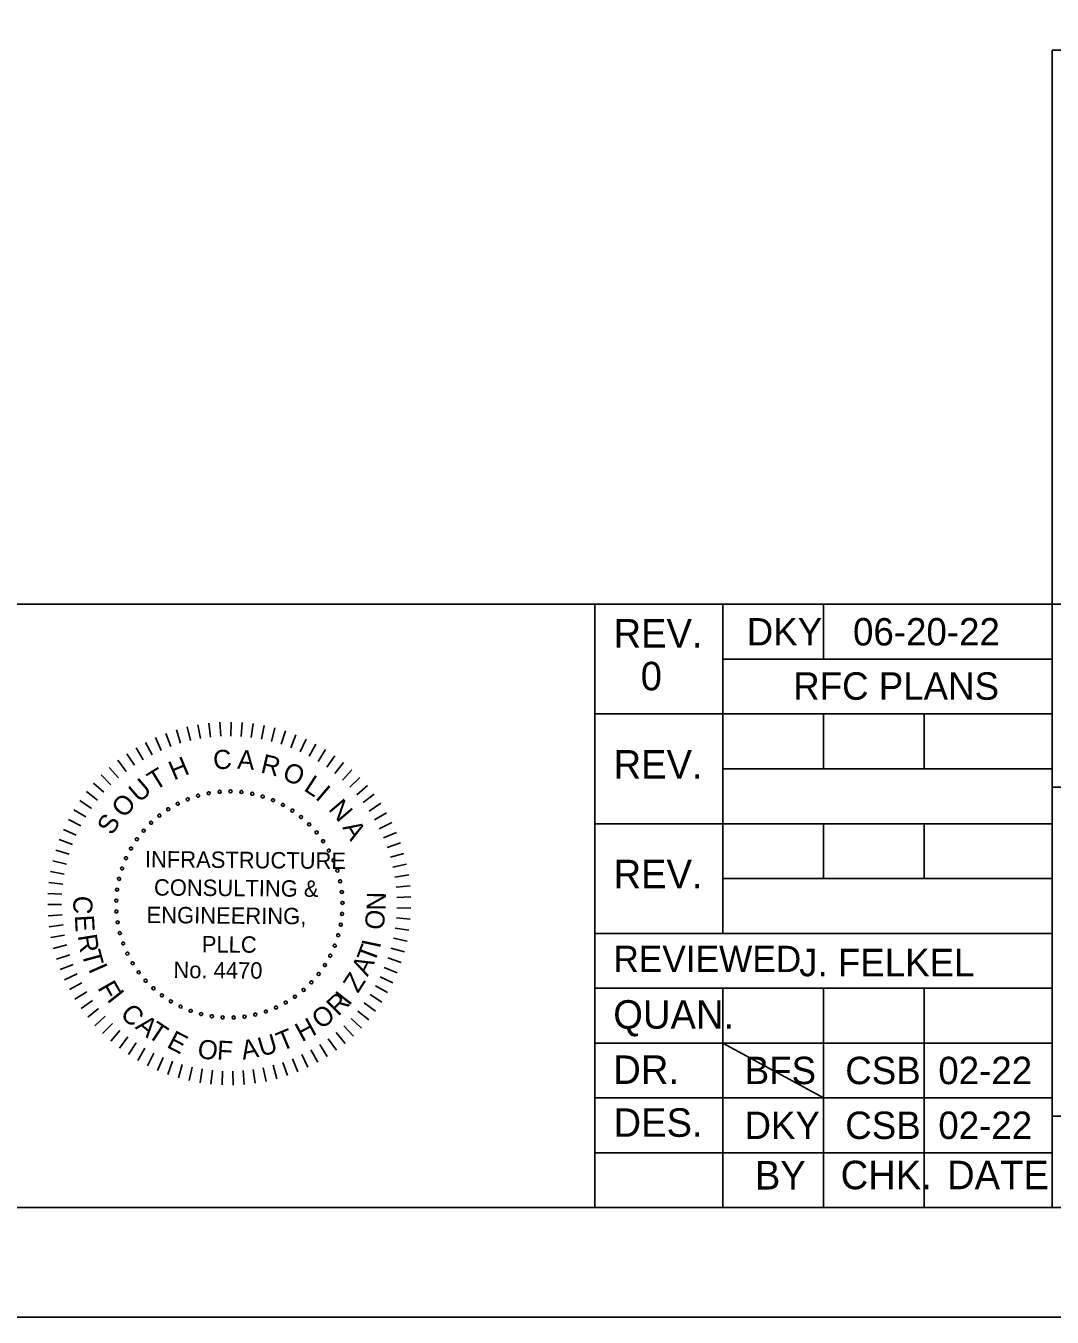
# Model space of a CAD drawing. Extents: x -133.1 to -97, y -1.7 to 20.3.
# Drawn here: x -107.74 to -103.06, y -1.69 to 4.2 of the extents above; entities that cross this region are included whole.
import ezdxf

# ---------------------------------------------------------------- set-up
doc = ezdxf.new("R2010")
doc.units = 0
for name, color, linetype in [('BR_BORDER LINES', 7, 'Continuous'), ('BR_TEXT', 7, 'Continuous'), ('Level 31', 7, 'Continuous')]:
    doc.layers.add(name, color=color, linetype=linetype)

msp = doc.modelspace()

# ---------------------------------------------------------------- linework, layer by layer
at = {"layer": 'BR_BORDER LINES'}
for p, q in [((-103.0585, -1.191), (-103.0585, 4.0855)), ((-103.0585, 4.0855), (-97.6416, 4.0855)), ((-110.5071, 1.5591), (-105.1419, 1.5591)), ((-105.1419, -1.191), (-105.1419, 1.5591)), ((-105.1419, 1.5591), (-97.6416, 1.5591)), ((-104.5585, 1.5591), (-104.5585, 0.059)), ((-104.1002, 1.3091), (-104.1002, 1.5591)), ((-104.5585, 1.3091), (-103.0585, 1.3091)), ((-105.1419, 1.0591), (-103.0585, 1.0591)), ((-104.1002, 0.809), (-104.1002, 1.0591)), ((-103.6418, 0.809), (-103.6418, 1.0591)), ((-104.5585, 0.809), (-103.0585, 0.809)), ((-103.0585, 0.7257), (-103.0585, 0.7257)), ((-103.0585, 0.7257), (-97.6414, 0.7257)), ((-105.1419, 0.559), (-103.0585, 0.559)), ((-104.1002, 0.309), (-104.1002, 0.559)), ((-103.6418, 0.309), (-103.6418, 0.559)), ((-104.5585, 0.309), (-103.0585, 0.309)), ((-105.1419, 0.059), (-103.0585, 0.059)), ((-105.1419, -0.191), (-103.0585, -0.191)), ((-104.5585, -0.191), (-104.5585, -1.191)), ((-104.1002, -0.191), (-104.1002, -1.191)), ((-103.6418, -0.191), (-103.6418, -1.191)), ((-105.1419, -0.441), (-103.0585, -0.441)), ((-105.1419, -0.691), (-103.0585, -0.691)), ((-103.0585, -0.7744), (-97.6416, -0.7744)), ((-105.1419, -0.941), (-103.0585, -0.941)), ((-131.3076, -1.191), (-97.6416, -1.191))]:
    msp.add_line(p, q, dxfattribs=at)
at = {"layer": 'BR_TEXT'}
for p, q in [((-106.9512, 1.01), (-106.9401, 0.9473)), ((-106.9012, 1.0172), (-106.894, 0.9539)), ((-106.8509, 1.0213), (-106.8476, 0.9578)), ((-106.8005, 1.0224), (-106.801, 0.9587)), ((-106.75, 1.0204), (-106.7544, 0.9569)), ((-106.6998, 1.0153), (-106.7081, 0.9522)), ((-106.65, 1.0071), (-106.6621, 0.9446)), ((-107.1439, 0.9513), (-107.1181, 0.8932)), ((-107.0972, 0.9704), (-107.0749, 0.9107)), ((-107.0494, 0.9866), (-107.0308, 0.9257)), ((-107.0007, 0.9998), (-106.9858, 0.9379)), ((-106.6007, 0.996), (-106.6166, 0.9343)), ((-106.5523, 0.9818), (-106.5719, 0.9213)), ((-106.5048, 0.9648), (-106.528, 0.9055)), ((-106.4584, 0.9448), (-106.4852, 0.8871)), ((-107.2335, 0.9049), (-107.2008, 0.8503)), ((-107.1895, 0.9295), (-107.1601, 0.873)), ((-106.4133, 0.9221), (-106.4436, 0.8661)), ((-106.3697, 0.8967), (-106.4034, 0.8426)), ((-107.3168, 0.8478), (-107.2776, 0.7976)), ((-107.276, 0.8776), (-107.24, 0.8251)), ((-106.3277, 0.8686), (-106.3646, 0.8167)), ((-106.2875, 0.8381), (-106.3275, 0.7885)), ((-107.3925, 0.7811), (-107.3475, 0.736)), ((-107.3557, 0.8156), (-107.3135, 0.7679)), ((-106.2493, 0.8051), (-106.2922, 0.7581)), ((-106.2131, 0.7699), (-106.2588, 0.7256)), ((-107.4272, 0.7444), (-107.3795, 0.7022)), ((-106.1791, 0.7326), (-106.2275, 0.6911)), ((-107.4895, 0.665), (-107.437, 0.6289)), ((-107.4595, 0.7056), (-107.4094, 0.6664)), ((-106.1475, 0.6932), (-106.1983, 0.6548)), ((-106.1184, 0.652), (-106.1714, 0.6167)), ((-107.5169, 0.6226), (-107.4623, 0.5897)), ((-106.0918, 0.6091), (-106.1469, 0.5771)), ((-107.5637, 0.5332), (-107.5055, 0.5072)), ((-107.5416, 0.5786), (-107.4852, 0.5491)), ((-106.0679, 0.5646), (-106.1248, 0.5361)), ((-107.5829, 0.4865), (-107.5233, 0.4641)), ((-106.0467, 0.5188), (-106.1052, 0.4938)), ((-106.0283, 0.4718), (-106.0883, 0.4504)), ((-107.5992, 0.4387), (-107.5384, 0.42)), ((-106.0129, 0.4237), (-106.0741, 0.406)), ((-107.6126, 0.3901), (-107.5507, 0.3751)), ((-106.0004, 0.3748), (-106.0625, 0.3608)), ((-107.623, 0.3407), (-107.5604, 0.3295)), ((-105.9909, 0.3252), (-106.0538, 0.3151)), ((-107.6348, 0.2404), (-107.5712, 0.237)), ((-107.6304, 0.2907), (-107.5672, 0.2834)), ((-105.9845, 0.2751), (-106.0479, 0.2689)), ((-107.636, 0.19), (-107.5723, 0.1904)), ((-105.9811, 0.2247), (-106.0448, 0.2224)), ((-107.6342, 0.1395), (-107.5706, 0.1438)), ((-105.9836, 0.1239), (-106.0471, 0.1292)), ((-105.9809, 0.1743), (-106.0445, 0.1758)), ((-107.6293, 0.0893), (-107.5661, 0.0974)), ((-105.9895, 0.0737), (-106.0525, 0.0829)), ((-107.6213, 0.0394), (-107.5588, 0.0514)), ((-107.6103, -0.0099), (-107.5487, 0.0059)), ((-105.9984, 0.024), (-106.0607, 0.0371)), ((-107.5964, -0.0584), (-107.5358, -0.0388)), ((-106.0252, -0.0733), (-106.0855, -0.0527)), ((-106.0103, -0.025), (-106.0717, -0.0082)), ((-107.5795, -0.106), (-107.5202, -0.0828)), ((-106.043, -0.1205), (-106.1019, -0.0963)), ((-107.5597, -0.1524), (-107.5019, -0.1256)), ((-107.5371, -0.1976), (-107.4811, -0.1673)), ((-106.0636, -0.1666), (-106.1209, -0.1389)), ((-107.5119, -0.2413), (-107.4578, -0.2077)), ((-106.1131, -0.2545), (-106.1667, -0.22)), ((-106.087, -0.2113), (-106.1426, -0.1802)), ((-107.484, -0.2834), (-107.4321, -0.2465)), ((-107.4536, -0.3237), (-107.404, -0.2837)), ((-106.1418, -0.2961), (-106.1931, -0.2584)), ((-107.4208, -0.362), (-107.3737, -0.3191)), ((-107.3857, -0.3983), (-107.3413, -0.3527)), ((-106.2065, -0.3735), (-106.2529, -0.3299)), ((-106.173, -0.3358), (-106.2219, -0.2951)), ((-107.3485, -0.4324), (-107.307, -0.3841)), ((-106.2801, -0.4426), (-106.3208, -0.3936)), ((-106.2423, -0.4092), (-106.2859, -0.3628)), ((-107.3092, -0.4642), (-107.2708, -0.4135)), ((-107.2681, -0.4935), (-107.2328, -0.4405)), ((-107.2253, -0.5203), (-107.1933, -0.4652)), ((-106.3616, -0.5021), (-106.3961, -0.4485)), ((-106.32, -0.4736), (-106.3576, -0.4222)), ((-107.1809, -0.5444), (-107.1523, -0.4875)), ((-107.1352, -0.5657), (-107.1101, -0.5072)), ((-107.0882, -0.5842), (-107.0668, -0.5243)), ((-106.5432, -0.5894), (-106.5637, -0.5291)), ((-106.4959, -0.5718), (-106.52, -0.5128)), ((-106.4498, -0.5513), (-106.4774, -0.4939)), ((-106.4049, -0.528), (-106.436, -0.4725)), ((-107.0402, -0.5998), (-107.0225, -0.5387)), ((-106.9913, -0.6125), (-106.9773, -0.5504)), ((-106.9418, -0.6221), (-106.9316, -0.5593)), ((-106.8918, -0.6288), (-106.8854, -0.5654)), ((-106.8414, -0.6323), (-106.8389, -0.5687)), ((-106.7909, -0.6328), (-106.7923, -0.5691)), ((-106.7405, -0.6302), (-106.7458, -0.5667)), ((-106.6903, -0.6245), (-106.6995, -0.5615)), ((-106.6406, -0.6158), (-106.6536, -0.5535)), ((-106.5915, -0.6041), (-106.6083, -0.5427))]:
    msp.add_line(p, q, dxfattribs=at)
for centre, start, end in [((-106.8527, 0.7043), 5.06529, 185.06529), ((-106.8029, 0.7062), 359.52683, 179.52683), ((-106.7531, 0.7033), 353.98837, 173.98837), ((-107.0431, 0.6496), 27.21914, 207.21914), ((-107.0431, 0.6496), 207.21914, 27.21914), ((-106.9977, 0.6702), 21.68068, 201.68068), ((-106.9977, 0.6702), 201.68068, 21.68068), ((-106.9506, 0.6862), 16.14222, 196.14222), ((-106.9506, 0.6862), 196.14222, 16.14222), ((-106.9021, 0.6977), 10.60376, 190.60376), ((-106.9021, 0.6977), 190.60376, 10.60376), ((-106.8527, 0.7043), 185.06529, 5.06529), ((-106.8029, 0.7062), 179.52683, 359.52683), ((-106.7531, 0.7033), 173.98837, 353.98837), ((-106.7039, 0.6956), 168.44991, 348.44991), ((-106.7039, 0.6956), 348.44991, 168.44991), ((-106.6557, 0.6832), 162.91145, 342.91145), ((-106.6557, 0.6832), 342.91145, 162.91145), ((-106.6088, 0.6662), 157.37299, 337.37299), ((-106.6088, 0.6662), 337.37299, 157.37299), ((-106.5639, 0.6447), 151.83453, 331.83453), ((-106.5639, 0.6447), 331.83453, 151.83453), ((-107.127, 0.5959), 38.29606, 218.29606), ((-107.127, 0.5959), 218.29606, 38.29606), ((-107.0864, 0.6248), 32.7576, 212.7576), ((-107.0864, 0.6248), 212.7576, 32.7576), ((-106.5212, 0.619), 146.29606, 326.29606), ((-106.5212, 0.619), 326.29606, 146.29606), ((-106.4811, 0.5893), 140.7576, 320.7576), ((-106.4811, 0.5893), 320.7576, 140.7576), ((-107.1989, 0.5271), 49.37299, 229.37299), ((-107.1989, 0.5271), 229.37299, 49.37299), ((-107.1646, 0.5633), 43.83453, 223.83453), ((-107.1646, 0.5633), 223.83453, 43.83453), ((-106.4442, 0.5559), 135.21914, 315.21914), ((-106.4442, 0.5559), 315.21914, 135.21914), ((-107.2296, 0.4879), 54.91145, 234.91145), ((-107.2296, 0.4879), 234.91145, 54.91145), ((-106.4106, 0.5191), 129.68068, 309.68068), ((-106.4106, 0.5191), 309.68068, 129.68068), ((-106.3808, 0.4792), 124.14222, 304.14222), ((-106.3808, 0.4792), 304.14222, 124.14222), ((-107.2563, 0.4458), 60.44991, 240.44991), ((-107.2563, 0.4458), 240.44991, 60.44991), ((-106.3549, 0.4366), 118.60376, 298.60376), ((-106.3549, 0.4366), 298.60376, 118.60376), ((-107.297, 0.3549), 71.52683, 251.52683), ((-107.297, 0.3549), 251.52683, 71.52683), ((-107.2788, 0.4014), 65.98837, 245.98837), ((-107.2788, 0.4014), 245.98837, 65.98837), ((-106.3333, 0.3917), 113.06529, 293.06529), ((-106.3333, 0.3917), 293.06529, 113.06529), ((-107.3106, 0.307), 77.06529, 257.06529), ((-107.3106, 0.307), 257.06529, 77.06529), ((-106.3161, 0.3449), 107.52683, 287.52683), ((-106.3161, 0.3449), 287.52683, 107.52683), ((-106.3035, 0.2967), 101.98837, 281.98837), ((-106.3035, 0.2967), 281.98837, 101.98837), ((-107.3195, 0.258), 82.60376, 262.60376), ((-107.3195, 0.258), 262.60376, 82.60376), ((-106.2956, 0.2475), 96.44991, 276.44991), ((-106.2956, 0.2475), 276.44991, 96.44991), ((-107.3236, 0.2083), 88.14222, 268.14222), ((-107.3236, 0.2083), 268.14222, 88.14222), ((-106.2925, 0.1977), 90.91145, 270.91145), ((-106.2925, 0.1977), 270.91145, 90.91145), ((-107.3229, 0.1585), 93.68068, 273.68068), ((-107.3229, 0.1585), 273.68068, 93.68068), ((-106.2942, 0.1479), 85.37299, 265.37299), ((-106.2942, 0.1479), 265.37299, 85.37299), ((-107.3174, 0.109), 99.21914, 279.21914), ((-107.3174, 0.109), 279.21914, 99.21914), ((-107.3071, 0.0602), 104.7576, 284.7576), ((-107.3071, 0.0602), 284.7576, 104.7576), ((-106.3007, 0.0985), 79.83453, 259.83453), ((-106.3007, 0.0985), 259.83453, 79.83453), ((-107.2922, 0.0126), 110.29606, 290.29606), ((-107.2922, 0.0126), 290.29606, 110.29606), ((-106.3279, 0.0028), 68.7576, 248.7576), ((-106.3279, 0.0028), 248.7576, 68.7576), ((-106.312, 0.05), 74.29606, 254.29606), ((-106.312, 0.05), 254.29606, 74.29606), ((-107.2728, -0.0332), 115.83453, 295.83453), ((-107.2728, -0.0332), 295.83453, 115.83453), ((-106.3483, -0.0427), 63.21914, 243.21914), ((-106.3483, -0.0427), 243.21914, 63.21914), ((-107.249, -0.077), 121.37299, 301.37299), ((-107.249, -0.077), 301.37299, 121.37299), ((-107.2211, -0.1183), 126.91145, 306.91145), ((-107.2211, -0.1183), 306.91145, 126.91145), ((-106.3729, -0.086), 57.68068, 237.68068), ((-106.3729, -0.086), 237.68068, 57.68068), ((-107.1894, -0.1567), 132.44991, 312.44991), ((-107.1894, -0.1567), 312.44991, 132.44991), ((-106.4342, -0.1645), 46.60376, 226.60376), ((-106.4342, -0.1645), 226.60376, 46.60376), ((-106.4016, -0.1267), 52.14222, 232.14222), ((-106.4016, -0.1267), 232.14222, 52.14222), ((-107.1541, -0.1919), 137.98837, 317.98837), ((-107.1541, -0.1919), 317.98837, 137.98837), ((-107.1156, -0.2235), 143.52683, 323.52683), ((-107.1156, -0.2235), 323.52683, 143.52683), ((-106.5093, -0.2297), 35.52683, 215.52683), ((-106.5093, -0.2297), 215.52683, 35.52683), ((-106.4702, -0.1989), 41.06529, 221.06529), ((-106.4702, -0.1989), 221.06529, 41.06529), ((-107.0742, -0.2512), 149.06529, 329.06529), ((-107.0742, -0.2512), 329.06529, 149.06529), ((-107.0303, -0.2749), 154.60376, 334.60376), ((-107.0303, -0.2749), 334.60376, 154.60376), ((-106.9843, -0.2941), 160.14222, 340.14222), ((-106.9843, -0.2941), 340.14222, 160.14222), ((-106.642, -0.2976), 18.91145, 198.91145), ((-106.5957, -0.2793), 24.44991, 204.44991), ((-106.5957, -0.2793), 204.44991, 24.44991), ((-106.5513, -0.2566), 29.98837, 209.98837), ((-106.5513, -0.2566), 209.98837, 29.98837), ((-106.9367, -0.3089), 165.68068, 345.68068), ((-106.9367, -0.3089), 345.68068, 165.68068), ((-106.8879, -0.3189), 171.21914, 351.21914), ((-106.8879, -0.3189), 351.21914, 171.21914), ((-106.8384, -0.3242), 356.7576, 176.7576), ((-106.8384, -0.3242), 176.7576, 356.7576), ((-106.7885, -0.3248), 2.29606, 182.29606), ((-106.7885, -0.3248), 182.29606, 2.29606), ((-106.7389, -0.3205), 7.83453, 187.83453), ((-106.7389, -0.3205), 187.83453, 7.83453), ((-106.6899, -0.3114), 13.37299, 193.37299), ((-106.6899, -0.3114), 193.37299, 13.37299), ((-106.642, -0.2976), 198.91145, 18.91145)]:
    msp.add_arc(centre, 0.00701, start, end, dxfattribs=at)
at = {"layer": 'Level 31'}
msp.add_line((-104.5585, -0.441), (-104.1002, -0.691), dxfattribs=at)
msp.add_lwpolyline([(-133.1409, -1.691), (-97.141, -1.691), (-97.141, 20.309), (-133.1409, 20.309)], close=True, dxfattribs=at)

# ---------------------------------------------------------------- texts
at = {"layer": 'BR_TEXT'}
for s, height, p in [('REV.', 0.13001, (-105.0572, 1.362)), ('DKY', 0.12499, (-104.4502, 1.3715)), ('06-20-22', 0.12499, (-103.9658, 1.3715)), ('0', 0.13, (-104.9333, 1.167)), ('RFC PLANS', 0.12499, (-104.2386, 1.124)), ('REV.', 0.13001, (-105.0572, 0.7645)), ('REV.', 0.13001, (-105.0572, 0.2644)), ('REVIEWED', 0.12, (-105.0579, -0.1175)), ('J. FELKEL', 0.125, (-104.2114, -0.1366)), ('QUAN.', 0.13001, (-105.0585, -0.3758)), ('DR.', 0.13001, (-105.0583, -0.6274)), ('BFS', 0.12499, (-104.4595, -0.6286)), ('CSB', 0.12499, (-104.0012, -0.6286)), ('02-22', 0.12499, (-103.5772, -0.6286)), ('DES.', 0.13001, (-105.0572, -0.8687)), ('DKY', 0.12499, (-104.4603, -0.8786)), ('CSB', 0.12499, (-104.0012, -0.8786)), ('02-22', 0.12499, (-103.5772, -0.8786)), ('BY', 0.13001, (-104.4132, -1.109)), ('CHK.', 0.13001, (-104.0224, -1.1077)), ('DATE', 0.13001, (-103.5372, -1.1076))]:
    msp.add_text(s, height=height, dxfattribs=at).set_placement(p)
for s, height, rotation, p in [('C', 0.0872, 4.72812, (-106.8784, 0.8048)), ('A', 0.0872, 355.69809, (-106.7739, 0.8098)), ('H', 0.0872, 22.78817, (-107.0612, 0.7554)), ('R', 0.0872, 346.66807, (-106.6696, 0.7928)), ('O', 0.0872, 337.63804, (-106.5719, 0.763)), ('U', 0.0872, 40.84822, (-107.2194, 0.6516)), ('T', 0.0872, 31.81819, (-107.1461, 0.7078)), ('L', 0.0872, 327.10802, (-106.4731, 0.7125)), ('I', 0.0872, 319.578, (-106.4205, 0.6747)), ('O', 0.0872, 49.87824, (-107.2864, 0.5806)), ('N', 0.0872, 310.54797, (-106.3597, 0.6239)), ('S', 0.0872, 58.90827, (-107.3418, 0.5024)), ('A', 0.0872, 301.51795, (-106.2946, 0.5415)), ('INFRASTRUCTURE', 0.074771, 359.52683, (-107.1932, 0.3599)), ('CONSULTING &', 0.074771, 359.52683, (-107.1519, 0.2313)), ('N', 0.0872, 89.20849, (-106.0953, 0.1628)), ('C', 0.0872, 267.02504, (-107.5168, 0.2325)), ('ENGINEERING,', 0.074771, 359.52683, (-107.1855, 0.1059)), ('E', 0.0872, 273.02504, (-107.5124, 0.1409)), ('O', 0.0872, 83.20849, (-106.1064, 0.0713)), ('R', 0.0872, 279.02504, (-107.4996, 0.0487)), ('PLLC', 0.07477, 359.52683, (-106.9338, -0.0277)), ('T', 0.0872, 69.39539, (-106.1476, -0.0805)), ('I', 0.0872, 77.90926, (-106.1219, -0.013)), ('T', 0.0872, 285.02504, (-107.4822, -0.0301)), ('I', 0.0872, 293.77127, (-107.4525, -0.1032)), ('No. 4470', 0.07477, 359.52683, (-107.0633, -0.1446)), ('Z', 0.0872, 57.39539, (-106.2222, -0.2172)), ('A', 0.0872, 63.39539, (-106.1784, -0.1408)), ('F', 0.0872, 299.77127, (-107.4113, -0.1893)), ('I', 0.0872, 308.52683, (-107.3692, -0.2431)), ('R', 0.0872, 44.52683, (-106.3127, -0.3221)), ('I', 0.0872, 52.33388, (-106.2633, -0.2748)), ('C', 0.0872, 314.52683, (-107.3099, -0.3133)), ('O', 0.0872, 38.52683, (-106.3893, -0.3821)), ('A', 0.0872, 320.52683, (-107.2407, -0.3718)), ('T', 0.0872, 326.52683, (-107.1863, -0.4103)), ('H', 0.0872, 28.52683, (-106.4774, -0.4381)), ('E', 0.0872, 332.52683, (-107.0977, -0.4581)), ('U', 0.0872, 16.52683, (-106.6623, -0.5042)), ('T', 0.0872, 22.52683, (-106.5706, -0.4799)), ('O', 0.0872, 350.52683, (-106.9576, -0.507)), ('F', 0.0872, 356.52683, (-106.8661, -0.5161)), ('A', 0.0872, 10.52683, (-106.7462, -0.5177))]:
    msp.add_text(s, height=height, rotation=rotation, dxfattribs=at).set_placement(p)

doc.saveas('drawing.dxf')
